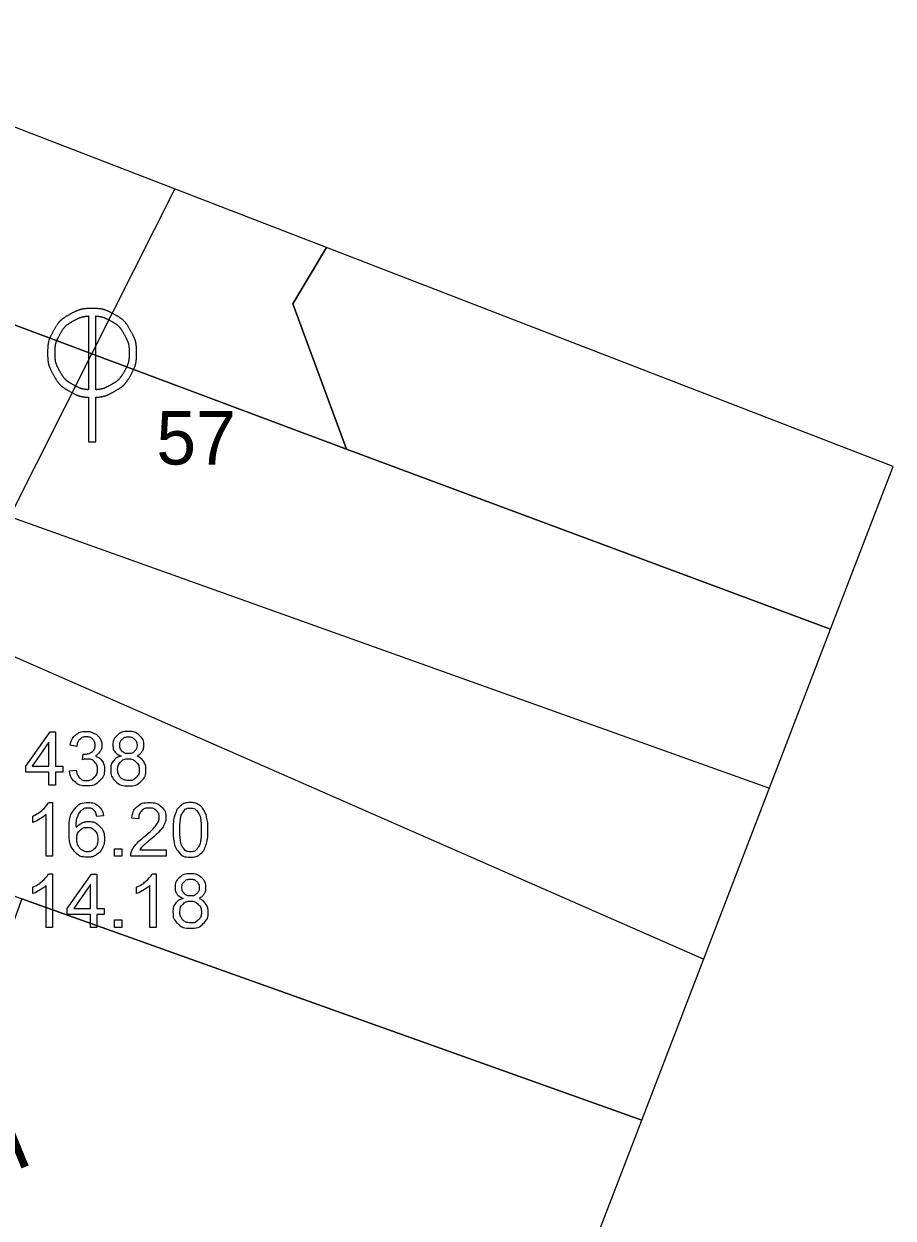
# Model space of a CAD drawing. Extents: x -562248 to -562040, y -1079385 to -1079027.
# Drawn here: x -562106.79 to -562082.36, y -1079065.59 to -1079032.03 of the extents above; entities that cross this region are included whole.
import ezdxf

# ---------------------------------------------------------------- set-up
doc = ezdxf.new("R2010")
doc.units = 0
for name, color, linetype in [('Armatura - popis', 7, 'Continuous'), ('Default', 7, 'Continuous'), ('Kanalizační stoka', 7, 'Continuous'), ('Kanalizační šachta', 7, 'Continuous'), ('Parcela-polygon', 7, 'Continuous'), ('Popis šachty', 7, 'Continuous'), ('Vodovodní řad', 7, 'Continuous')]:
    doc.layers.add(name, color=color, linetype=linetype)

msp = doc.modelspace()

# ---------------------------------------------------------------- linework, layer by layer
at = {"layer": 'Default'}
for points in [[(-562104.87, -1079040.027), (-562105.082, -1079040.027), (-562105.287, -1079040.081), (-562105.485, -1079040.188)], [(-562104.256, -1079040.188), (-562104.455, -1079040.081), (-562104.66, -1079040.027), (-562104.87, -1079040.027)], [(-562105.485, -1079040.188), (-562105.684, -1079040.296), (-562105.839, -1079040.449), (-562105.952, -1079040.65)], [(-562105.773, -1079040.756), (-562105.681, -1079040.589), (-562105.551, -1079040.461), (-562105.385, -1079040.371)], [(-562105.385, -1079040.371), (-562105.242, -1079040.295), (-562105.104, -1079040.251), (-562104.973, -1079040.239)], [(-562104.767, -1079040.239), (-562104.636, -1079040.251), (-562104.499, -1079040.295), (-562104.357, -1079040.371)], [(-562104.357, -1079040.371), (-562104.191, -1079040.461), (-562104.061, -1079040.589), (-562103.968, -1079040.756)], [(-562103.788, -1079040.65), (-562103.901, -1079040.449), (-562104.057, -1079040.296), (-562104.256, -1079040.188)], [(-562105.952, -1079040.65), (-562106.064, -1079040.85), (-562106.12, -1079041.059), (-562106.12, -1079041.277)], [(-562105.912, -1079041.277), (-562105.912, -1079041.096), (-562105.866, -1079040.923), (-562105.773, -1079040.756)], [(-562103.968, -1079040.756), (-562103.874, -1079040.923), (-562103.828, -1079041.096), (-562103.828, -1079041.277)], [(-562103.62, -1079041.277), (-562103.62, -1079041.059), (-562103.676, -1079040.85), (-562103.788, -1079040.65)], [(-562106.12, -1079041.277), (-562106.12, -1079041.493), (-562106.065, -1079041.701), (-562105.955, -1079041.9)], [(-562105.776, -1079041.795), (-562105.867, -1079041.63), (-562105.912, -1079041.458), (-562105.912, -1079041.277)], [(-562103.828, -1079041.277), (-562103.828, -1079041.458), (-562103.873, -1079041.63), (-562103.964, -1079041.795)], [(-562103.785, -1079041.9), (-562103.675, -1079041.701), (-562103.62, -1079041.493), (-562103.62, -1079041.277)], [(-562105.955, -1079041.9), (-562105.845, -1079042.098), (-562105.691, -1079042.252), (-562105.493, -1079042.361)], [(-562105.39, -1079042.178), (-562105.556, -1079042.087), (-562105.685, -1079041.959), (-562105.776, -1079041.795)], [(-562103.964, -1079041.795), (-562104.055, -1079041.959), (-562104.183, -1079042.087), (-562104.348, -1079042.178)], [(-562104.247, -1079042.361), (-562104.049, -1079042.252), (-562103.895, -1079042.098), (-562103.785, -1079041.9)], [(-562105.493, -1079042.361), (-562105.318, -1079042.459), (-562105.145, -1079042.513), (-562104.973, -1079042.525)], [(-562104.973, -1079042.312), (-562105.109, -1079042.302), (-562105.248, -1079042.258), (-562105.39, -1079042.178)], [(-562104.348, -1079042.178), (-562104.491, -1079042.258), (-562104.631, -1079042.302), (-562104.767, -1079042.312)], [(-562104.767, -1079042.525), (-562104.595, -1079042.513), (-562104.422, -1079042.459), (-562104.247, -1079042.361)]]:
    msp.add_open_spline(points, degree=2, dxfattribs=at)
at = {"layer": 'Kanalizační stoka'}
for points in [[(-562102.548, -1079036.668), (-562104.87, -1079041.277)], [(-562104.87, -1079041.277), (-562108.79, -1079049.06)], [(-562087.687, -1079058.312), (-562108.79, -1079049.06)]]:
    msp.add_lwpolyline(points, dxfattribs=at)
at = {"layer": 'Kanalizační šachta'}
for points in [[(-562104.973, -1079040.239), (-562104.973, -1079042.312)], [(-562104.767, -1079042.312), (-562104.767, -1079040.239)], [(-562104.973, -1079043.777), (-562104.767, -1079043.777), (-562104.767, -1079042.525)], [(-562104.973, -1079042.525), (-562104.973, -1079043.777)]]:
    msp.add_lwpolyline(points, dxfattribs=at)
at = {"layer": 'Parcela-polygon'}
for p, q in [((-562098.282, -1079038.318), (-562109.587, -1079033.946)), ((-562089.427, -1079062.836), (-562084.12, -1079049.039))]:
    msp.add_line(p, q, dxfattribs=at)
for points in [[(-562084.12, -1079049.039), (-562097.72, -1079043.98), (-562114.77, -1079037.6), (-562129.957, -1079032.03)], [(-562109.587, -1079033.946), (-562111, -1079036.29), (-562114.77, -1079037.6), (-562097.72, -1079043.98), (-562099.23, -1079039.9), (-562098.282, -1079038.318)], [(-562098.282, -1079038.318), (-562099.23, -1079039.9), (-562097.72, -1079043.98), (-562084.12, -1079049.039)], [(-562084.12, -1079049.039), (-562082.364, -1079044.473), (-562098.282, -1079038.318)], [(-562134.941, -1079046.267), (-562116.62, -1079052.94), (-562106.84, -1079056.62), (-562089.427, -1079062.836)], [(-562089.427, -1079062.836), (-562106.84, -1079056.62), (-562119.65, -1079091.82), (-562121.03, -1079096.76), (-562122.05, -1079101.16), (-562122.69, -1079105.05), (-562122.92, -1079108.96), (-562097.98, -1079104.526)], [(-562097.98, -1079104.526), (-562101.498, -1079094.222), (-562089.427, -1079062.836)]]:
    msp.add_lwpolyline(points, dxfattribs=at)
at = {"layer": 'Popis šachty'}
for points in [[(-562106.082, -1079053.422), (-562106.082, -1079053.063), (-562106.732, -1079053.063), (-562106.732, -1079052.894), (-562106.049, -1079051.922), (-562105.898, -1079051.922), (-562105.898, -1079052.894), (-562105.695, -1079052.894), (-562105.695, -1079053.063), (-562105.898, -1079053.063), (-562105.898, -1079053.422), (-562106.082, -1079053.422)], [(-562106.082, -1079052.894), (-562106.082, -1079052.217), (-562106.551, -1079052.894), (-562106.082, -1079052.894)], [(-562105.303, -1079052.338), (-562105.487, -1079052.305)], [(-562105.143, -1079052.711), (-562105.122, -1079052.55)], [(-562105.506, -1079053.024), (-562105.322, -1079053)], [(-562106.098, -1079053.916), (-562105.979, -1079053.916), (-562105.979, -1079055.422)], [(-562106.531, -1079054.471), (-562106.531, -1079054.293)], [(-562105.979, -1079055.422), (-562106.163, -1079055.422), (-562106.163, -1079054.249)], [(-562104.55, -1079054.29), (-562104.733, -1079054.305)], [(-562103.56, -1079054.369), (-562103.75, -1079054.35)], [(-562104.239, -1079055.422), (-562104.239, -1079055.213), (-562104.03, -1079055.213), (-562104.03, -1079055.422), (-562104.239, -1079055.422)], [(-562102.793, -1079055.245), (-562102.793, -1079055.422), (-562103.784, -1079055.422)], [(-562103.528, -1079055.245), (-562102.793, -1079055.245)], [(-562106.098, -1079055.916), (-562105.979, -1079055.916), (-562105.979, -1079057.422)], [(-562104.917, -1079057.422), (-562104.917, -1079057.063), (-562105.567, -1079057.063), (-562105.567, -1079056.894), (-562104.884, -1079055.922), (-562104.733, -1079055.922), (-562104.733, -1079056.894), (-562104.53, -1079056.894), (-562104.53, -1079057.063), (-562104.733, -1079057.063), (-562104.733, -1079057.422), (-562104.917, -1079057.422)], [(-562103.186, -1079055.916), (-562103.067, -1079055.916), (-562103.067, -1079057.422)], [(-562106.531, -1079056.471), (-562106.531, -1079056.293)], [(-562105.979, -1079057.422), (-562106.163, -1079057.422), (-562106.163, -1079056.249)], [(-562104.917, -1079056.894), (-562104.917, -1079056.217), (-562105.386, -1079056.894), (-562104.917, -1079056.894)], [(-562103.619, -1079056.471), (-562103.619, -1079056.293)], [(-562103.067, -1079057.422), (-562103.251, -1079057.422), (-562103.251, -1079056.249)], [(-562104.239, -1079057.422), (-562104.239, -1079057.213), (-562104.03, -1079057.213), (-562104.03, -1079057.422), (-562104.239, -1079057.422)]]:
    msp.add_lwpolyline(points, dxfattribs=at)
for points in [[(-562105.487, -1079052.305), (-562105.454, -1079052.12), (-562105.334, -1079052.018), (-562105.214, -1079051.916), (-562105.036, -1079051.916), (-562104.913, -1079051.916), (-562104.81, -1079051.969), (-562104.706, -1079052.022), (-562104.652, -1079052.112), (-562104.597, -1079052.203), (-562104.597, -1079052.305), (-562104.597, -1079052.403), (-562104.649, -1079052.482), (-562104.701, -1079052.562), (-562104.803, -1079052.609), (-562104.67, -1079052.64), (-562104.597, -1079052.736), (-562104.524, -1079052.833), (-562104.524, -1079052.978), (-562104.524, -1079053.174), (-562104.667, -1079053.311), (-562104.81, -1079053.447), (-562105.029, -1079053.447), (-562105.226, -1079053.447), (-562105.357, -1079053.329), (-562105.487, -1079053.212), (-562105.506, -1079053.024)], [(-562105.122, -1079052.55), (-562105.104, -1079052.552), (-562105.092, -1079052.552), (-562104.975, -1079052.552), (-562104.881, -1079052.49), (-562104.787, -1079052.429), (-562104.787, -1079052.301), (-562104.787, -1079052.2), (-562104.855, -1079052.134), (-562104.924, -1079052.067), (-562105.032, -1079052.067), (-562105.14, -1079052.067), (-562105.211, -1079052.135), (-562105.283, -1079052.203), (-562105.303, -1079052.338)], [(-562104.057, -1079052.608), (-562104.172, -1079052.566), (-562104.228, -1079052.488), (-562104.283, -1079052.411), (-562104.283, -1079052.302), (-562104.283, -1079052.139), (-562104.166, -1079052.028), (-562104.048, -1079051.916), (-562103.853, -1079051.916), (-562103.657, -1079051.916), (-562103.538, -1079052.03), (-562103.418, -1079052.144), (-562103.418, -1079052.308), (-562103.418, -1079052.412), (-562103.473, -1079052.489), (-562103.528, -1079052.566), (-562103.639, -1079052.608), (-562103.501, -1079052.653), (-562103.429, -1079052.753), (-562103.356, -1079052.854), (-562103.356, -1079052.993), (-562103.356, -1079053.185), (-562103.492, -1079053.316), (-562103.628, -1079053.447), (-562103.85, -1079053.447), (-562104.072, -1079053.447), (-562104.208, -1079053.316), (-562104.344, -1079053.184), (-562104.344, -1079052.988), (-562104.344, -1079052.841), (-562104.27, -1079052.743), (-562104.195, -1079052.644), (-562104.057, -1079052.608)], [(-562104.094, -1079052.296), (-562104.094, -1079052.402), (-562104.026, -1079052.47), (-562103.958, -1079052.537), (-562103.849, -1079052.537), (-562103.742, -1079052.537), (-562103.675, -1079052.47), (-562103.608, -1079052.403), (-562103.608, -1079052.306), (-562103.608, -1079052.205), (-562103.677, -1079052.136), (-562103.747, -1079052.067), (-562103.851, -1079052.067), (-562103.956, -1079052.067), (-562104.025, -1079052.135), (-562104.094, -1079052.202), (-562104.094, -1079052.296)], [(-562105.322, -1079053), (-562105.29, -1079053.157), (-562105.214, -1079053.226), (-562105.138, -1079053.295), (-562105.028, -1079053.295), (-562104.898, -1079053.295), (-562104.808, -1079053.205), (-562104.719, -1079053.115), (-562104.719, -1079052.982), (-562104.719, -1079052.855), (-562104.802, -1079052.773), (-562104.885, -1079052.69), (-562105.013, -1079052.69), (-562105.065, -1079052.69), (-562105.143, -1079052.711)], [(-562104.154, -1079052.989), (-562104.154, -1079053.068), (-562104.117, -1079053.142), (-562104.081, -1079053.215), (-562104.007, -1079053.256), (-562103.933, -1079053.296), (-562103.849, -1079053.296), (-562103.717, -1079053.296), (-562103.631, -1079053.211), (-562103.546, -1079053.126), (-562103.546, -1079052.995), (-562103.546, -1079052.862), (-562103.634, -1079052.775), (-562103.722, -1079052.688), (-562103.855, -1079052.688), (-562103.985, -1079052.688), (-562104.07, -1079052.774), (-562104.154, -1079052.86), (-562104.154, -1079052.989)], [(-562106.531, -1079054.293), (-562106.377, -1079054.22), (-562106.261, -1079054.117), (-562106.146, -1079054.013), (-562106.098, -1079053.916)], [(-562104.733, -1079054.305), (-562104.757, -1079054.196), (-562104.803, -1079054.146), (-562104.877, -1079054.067), (-562104.987, -1079054.067), (-562105.075, -1079054.067), (-562105.143, -1079054.116), (-562105.229, -1079054.18), (-562105.28, -1079054.302), (-562105.33, -1079054.423), (-562105.332, -1079054.649), (-562105.265, -1079054.547), (-562105.169, -1079054.498), (-562105.073, -1079054.449), (-562104.967, -1079054.449), (-562104.783, -1079054.449), (-562104.653, -1079054.585), (-562104.524, -1079054.72), (-562104.524, -1079054.935), (-562104.524, -1079055.076), (-562104.585, -1079055.197), (-562104.645, -1079055.318), (-562104.752, -1079055.383), (-562104.858, -1079055.447), (-562104.994, -1079055.447), (-562105.224, -1079055.447), (-562105.369, -1079055.278), (-562105.515, -1079055.109), (-562105.515, -1079054.72), (-562105.515, -1079054.285), (-562105.354, -1079054.088), (-562105.214, -1079053.916), (-562104.976, -1079053.916), (-562104.799, -1079053.916), (-562104.686, -1079054.016), (-562104.572, -1079054.115), (-562104.55, -1079054.29)], [(-562103.784, -1079055.422), (-562103.786, -1079055.355), (-562103.762, -1079055.294), (-562103.724, -1079055.193), (-562103.641, -1079055.094), (-562103.558, -1079054.996), (-562103.4, -1079054.868), (-562103.156, -1079054.667), (-562103.07, -1079054.55), (-562102.985, -1079054.433), (-562102.985, -1079054.328), (-562102.985, -1079054.219), (-562103.063, -1079054.143), (-562103.141, -1079054.068), (-562103.267, -1079054.068), (-562103.399, -1079054.068), (-562103.479, -1079054.148), (-562103.559, -1079054.228), (-562103.56, -1079054.369)], [(-562103.75, -1079054.35), (-562103.73, -1079054.138), (-562103.603, -1079054.027), (-562103.476, -1079053.916), (-562103.263, -1079053.916), (-562103.047, -1079053.916), (-562102.921, -1079054.036), (-562102.795, -1079054.156), (-562102.795, -1079054.332), (-562102.795, -1079054.422), (-562102.832, -1079054.509), (-562102.869, -1079054.596), (-562102.954, -1079054.692), (-562103.039, -1079054.789), (-562103.237, -1079054.956), (-562103.403, -1079055.095), (-562103.45, -1079055.145), (-562103.497, -1079055.195), (-562103.528, -1079055.245)], [(-562102.595, -1079054.682), (-562102.595, -1079054.416), (-562102.54, -1079054.254), (-562102.485, -1079054.092), (-562102.378, -1079054.004), (-562102.27, -1079053.916), (-562102.106, -1079053.916), (-562101.985, -1079053.916), (-562101.894, -1079053.965), (-562101.803, -1079054.013), (-562101.744, -1079054.105), (-562101.685, -1079054.196), (-562101.651, -1079054.328), (-562101.617, -1079054.459), (-562101.617, -1079054.682), (-562101.617, -1079054.946), (-562101.672, -1079055.108), (-562101.726, -1079055.271), (-562101.834, -1079055.359), (-562101.941, -1079055.447), (-562102.106, -1079055.447), (-562102.323, -1079055.447), (-562102.447, -1079055.292), (-562102.595, -1079055.105), (-562102.595, -1079054.682)], [(-562102.405, -1079054.682), (-562102.405, -1079055.052), (-562102.319, -1079055.174), (-562102.233, -1079055.296), (-562102.106, -1079055.296), (-562101.98, -1079055.296), (-562101.893, -1079055.174), (-562101.807, -1079055.051), (-562101.807, -1079054.682), (-562101.807, -1079054.312), (-562101.893, -1079054.19), (-562101.979, -1079054.068), (-562102.108, -1079054.068), (-562102.235, -1079054.068), (-562102.31, -1079054.176), (-562102.405, -1079054.313), (-562102.405, -1079054.682)], [(-562106.163, -1079054.249), (-562106.23, -1079054.312), (-562106.337, -1079054.376), (-562106.445, -1079054.439), (-562106.531, -1079054.471)], [(-562105.303, -1079054.936), (-562105.303, -1079055.031), (-562105.263, -1079055.118), (-562105.223, -1079055.205), (-562105.15, -1079055.251), (-562105.078, -1079055.296), (-562104.998, -1079055.296), (-562104.88, -1079055.296), (-562104.797, -1079055.202), (-562104.713, -1079055.108), (-562104.713, -1079054.946), (-562104.713, -1079054.791), (-562104.796, -1079054.701), (-562104.878, -1079054.611), (-562105.005, -1079054.611), (-562105.129, -1079054.611), (-562105.216, -1079054.701), (-562105.303, -1079054.791), (-562105.303, -1079054.936)], [(-562106.531, -1079056.293), (-562106.377, -1079056.22), (-562106.261, -1079056.117), (-562106.146, -1079056.013), (-562106.098, -1079055.916)], [(-562103.619, -1079056.293), (-562103.465, -1079056.22), (-562103.349, -1079056.117), (-562103.234, -1079056.013), (-562103.186, -1079055.916)], [(-562102.31, -1079056.608), (-562102.425, -1079056.566), (-562102.481, -1079056.488), (-562102.537, -1079056.411), (-562102.537, -1079056.302), (-562102.537, -1079056.139), (-562102.419, -1079056.028), (-562102.302, -1079055.916), (-562102.106, -1079055.916), (-562101.91, -1079055.916), (-562101.791, -1079056.03), (-562101.671, -1079056.144), (-562101.671, -1079056.308), (-562101.671, -1079056.412), (-562101.726, -1079056.489), (-562101.781, -1079056.566), (-562101.892, -1079056.608), (-562101.754, -1079056.653), (-562101.682, -1079056.753), (-562101.609, -1079056.854), (-562101.609, -1079056.993), (-562101.609, -1079057.185), (-562101.745, -1079057.316), (-562101.881, -1079057.447), (-562102.103, -1079057.447), (-562102.325, -1079057.447), (-562102.461, -1079057.316), (-562102.597, -1079057.184), (-562102.597, -1079056.988), (-562102.597, -1079056.841), (-562102.523, -1079056.743), (-562102.448, -1079056.644), (-562102.31, -1079056.608)], [(-562102.347, -1079056.296), (-562102.347, -1079056.402), (-562102.279, -1079056.47), (-562102.211, -1079056.537), (-562102.102, -1079056.537), (-562101.995, -1079056.537), (-562101.928, -1079056.47), (-562101.861, -1079056.403), (-562101.861, -1079056.306), (-562101.861, -1079056.205), (-562101.93, -1079056.136), (-562102, -1079056.067), (-562102.104, -1079056.067), (-562102.209, -1079056.067), (-562102.278, -1079056.135), (-562102.347, -1079056.202), (-562102.347, -1079056.296)], [(-562106.163, -1079056.249), (-562106.23, -1079056.312), (-562106.337, -1079056.376), (-562106.445, -1079056.439), (-562106.531, -1079056.471)], [(-562103.251, -1079056.249), (-562103.318, -1079056.312), (-562103.425, -1079056.376), (-562103.533, -1079056.439), (-562103.619, -1079056.471)], [(-562102.407, -1079056.989), (-562102.407, -1079057.068), (-562102.37, -1079057.142), (-562102.334, -1079057.215), (-562102.26, -1079057.256), (-562102.186, -1079057.296), (-562102.102, -1079057.296), (-562101.97, -1079057.296), (-562101.884, -1079057.211), (-562101.799, -1079057.126), (-562101.799, -1079056.995), (-562101.799, -1079056.862), (-562101.887, -1079056.775), (-562101.975, -1079056.688), (-562102.108, -1079056.688), (-562102.238, -1079056.688), (-562102.323, -1079056.774), (-562102.407, -1079056.86), (-562102.407, -1079056.989)]]:
    msp.add_open_spline(points, degree=3, dxfattribs=at)
at = {"layer": 'Vodovodní řad'}
msp.add_lwpolyline([(-562112.389, -1079044.02), (-562111.645, -1079044.286), (-562085.841, -1079053.513)], dxfattribs=at)

# ---------------------------------------------------------------- texts
at = {"layer": 'Armatura - popis'}
msp.add_text('SU-815', height=2, rotation=292.2406, dxfattribs=at).set_placement((-562111.854, -1079056.681))
at = {"layer": 'Popis šachty'}
msp.add_text('57', height=1.5, dxfattribs=at).set_placement((-562103.064, -1079044.413))

doc.saveas('drawing.dxf')
